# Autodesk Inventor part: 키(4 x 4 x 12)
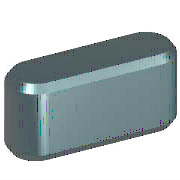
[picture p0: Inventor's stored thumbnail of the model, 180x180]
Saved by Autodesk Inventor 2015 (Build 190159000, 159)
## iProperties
IsCustomPart: 0
Created: 2009-02
Part Number: 키(4 x 4 x 12)
Material: 강철, 연강
Description: 키 및 해당 키홈
Document SubType Name: Modeling
Standard: KS B 1311
Designer: KYOUNG IL JANG
Standards Organization: KS
Language: ko-KR
Size Designation: 4 x 4 x 12
Categories: <MemberInstance><Categories><Category DisplayName="샤프트 부품" InternalName="7f7aeb1f-a693-4053-b835-cee3144e0d98" Mnemonic="SHFT"><Category DisplayName="키" Interna
Density: 7.86 g/cm^3
Mass: 1.38739 g
Surface Area: 1.94869 cm^2
Volume: 0.176513 cm^3
Appearance: 강철
Author: KYOUNG IL JANG
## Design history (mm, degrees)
workplane "Work Plane1"
workplane "Work Plane2"
sketch "스케치1"
  geometry: L1 (2, 2)-(10, 2); L2 (10, -2)-(2, -2); L3 (0, 9.4)-(0, -7.4) reference; L4 (-5, 0)-(30, 0) reference; L5 (12, 0)-(12, 7); A1 r 2 centre (2, 0) between (2, 2) and (2, -2); A2 r 2 centre (10, 0) between (10, -2) and (10, 2)
  constraints: 6 end point, 5 point on circle, 4 tangent, 3 point on line, 2 centre point, 1 horizontal, 1 parallel, 1 perpendicular
  dimensions: "d0" = 2 radius of A1 (= 0.5 x PB); "d13" = 2 radius of A2 (= 0.5 x PB); "d14" = 12 distance between parallel lines of L5 L3 (= NLG)
extrude "본체1" new body sketch "스케치1" taper "d3" = 0 deg; stored distance "d4" = 10
workplane "Work Plane3"
body "Solid1"
chamfer "모따기1" distance "d8" = 0.25 (= PHH); stored, may be unused: second distance "d9" = 0.25 (= PHH), angle "d15" = 45 deg
other parameters: "d1" = -2.5 (= -PNT), "d2" = 1.5 (= PH - PNT), "NLG" = 12 [user parameter; used in 3 equation terms], "PB" = 4 [user parameter; used in 2 equation terms], "PNT" = 2.5 [user parameter; used in 2 equation terms], "PH" = 4 [user parameter; used in 1 equation term], "PHH" = 0.25 [user parameter; used in 2 equation terms], "d10" = 0, "d16" = 0, "d17" = 0, "d18" = 0, "PLB2" = 12 (= NLG) [user parameter], "WDMAX" = 12 [user parameter], "PLB1" = 12 (= NLG) [user parameter], "RR" = 0.08 [user parameter], "PUEB" = 1.8 [user parameter]
